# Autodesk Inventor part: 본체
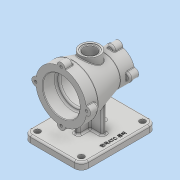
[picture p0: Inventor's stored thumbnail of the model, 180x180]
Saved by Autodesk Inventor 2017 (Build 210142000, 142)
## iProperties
Part Number: 본체
Material: 일반
Document SubType Name: Modeling
Designer: mrc
Density: 1 g/cm^3
Appearance: 기본값
Mass: 381.324 g
Surface Area: 851.607 cm^2
Volume: 381.324 cm^3
Author: mrc
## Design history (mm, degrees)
sketch "스케치3"
  geometry: L1 (-50, 0)-(-50, 44); L2 (-50, 44)-(-30, 44); L3 (-30, 44)-(25, 27.5); L4 (25, 27.5)-(50, 27.5); L5 (50, 27.5)-(50, 0); L6 (50, 0)-(-50, 0); 2 further points
  constraints: 12 end point, 2 horizontal, 2 perpendicular, 1 coincident, 1 midpoint, 1 vertical
  dimensions: "d29" = 44 distance of L1.start L1.end; "d30" = 20 distance of L1.end L2.end; "d31" = 100 distance between parallel lines of L5 L1; "d32" = 27.5 distance of L4.end L5.end; "d33" = 25 distance of L3.end L4.end
node "스케치4"
revolve "회전1" stored, may be unused: angle "d34" = 90 deg
sketch "스케치5"
  geometry: L1 (65, -70)-(-65, -70); L2 (-65, -70)-(-65, -82); L3 (-65, -82)-(65, -82); L4 (65, -82)-(65, -70); 2 further points
  constraints: 8 end point, 2 parallel, 1 horizontal, 1 midpoint, 1 perpendicular, 1 vertical alignment
  dimensions: "d35" = 130 distance of L3.end L2.end; "d36" = 12 distance of L2.end L1.end; "d37" = 82 vertical distance of L3.end point (0, 0)
extrude "돌출1" join sketch "스케치5" stored distance "d38" = 100; taper "d39" = 0 deg
sketch "스케치6"
  geometry: L1 (-24, 2.047)-(24, 2.047); L2 (24, 2.047)-(24, -70); L3 (24, -70)-(-24, -70); L4 (-24, -70)-(-24, 2.047); L5 (-65, -70)-(65, -70) reference; 2 further points
  constraints: 8 end point, 2 midpoint, 2 parallel, 1 horizontal, 1 perpendicular
  dimensions: "d40" = 48 distance of L2.end L3.end
extrude "돌출2" join sketch "스케치6" stored distance "d41" = 8; taper "d42" = 0 deg
sketch "스케치7"
  geometry: L1 (25, -3.867)-(-25, -3.867); L2 (-25, -3.867)-(-25, -70); L3 (-25, -70)-(25, -70); L4 (25, -70)-(25, -3.867); L5 (4, -70)-(-4, -70) reference; 2 further points
  constraints: 8 end point, 2 midpoint, 2 parallel, 1 horizontal, 1 perpendicular
  dimensions: "d43" = 50 distance of L3.end L2.end
extrude "돌출3" join sketch "스케치7" stored distance "d44" = 8; taper "d45" = 0 deg
sketch "스케치8"
  geometry: C1 r 32 at (0, 0); 1 further point
  constraints: 1 centre point, 1 coincident
  dimensions: "d46" = 64 diameter of C1
extrude "돌출4" cut sketch "스케치8" distance "d47" = 23; taper "d48" = 0 deg
sketch "스케치9"
  geometry: C1 r 26 at (0, 0); 1 further point
  constraints: 1 centre point, 1 coincident
  dimensions: "d49" = 52 diameter of C1
extrude "돌출5" cut sketch "스케치9" distance "d50" = 47; taper "d51" = 0 deg
sketch "스케치10"
  geometry: C1 r 20 at (0, 0); 1 further point
  constraints: 1 centre point, 1 coincident
  dimensions: "d52" = 40 diameter of C1
extrude "돌출6" cut sketch "스케치10" distance "d53" = 30; taper "d54" = 0 deg
sketch "스케치11"
  geometry: C1 r 7 at (0, 44); 2 further points
  constraints: 1 centre point, 1 vertical alignment, 1 other
  dimensions: "d55" = 14 diameter of C1
extrude "돌출7" join sketch "스케치11" distance "d56" = 15; taper "d57" = 0 deg
hole "구멍1" diameter "d60" = 4.459; stored, may be unused: countersink angle "d64" = 90 deg, drill point angle "d66" = 118 deg; dims "d58" = 10, "d59" = 10, "d61" = 9, "d62" = 4, "d63" = 2, "d65" = 11
sketch "스케치12"
  geometry: C1 r 7 at (0, -27.5); 2 further points
  constraints: 1 centre point, 1 vertical alignment, 1 other
  dimensions: "d70" = 14 diameter of C1
extrude "돌출8" join sketch "스케치12" distance "d71" = 15; taper "d72" = 0 deg
hole "구멍2" diameter "d75" = 4.459; stored, may be unused: countersink angle "d79" = 90 deg, drill point angle "d81" = 118 deg; dims "d73" = 10, "d74" = 10, "d76" = 9, "d77" = 4, "d78" = 2, "d80" = 11
node "작업 평면1"
sketch "스케치13"
  geometry: C1 r 17 at (0, 0); 1 further point
  constraints: 1 centre point, 1 coincident
  dimensions: "d86" = 34 diameter of C1
extrude "돌출9" join sketch "스케치13" stored distance "d87" = 15; taper "d88" = 0 deg
sketch "스케치14"
  geometry: C1 r 14 at (0, 0); 1 further point
  constraints: 1 centre point, 1 coincident
  dimensions: "d89" = 28 diameter of C1
extrude "돌출10" cut sketch "스케치14" distance "d90" = 1; taper "d91" = 0 deg
sketch "스케치15"
  geometry: C1 r 11 at (0, 0); 1 further point
  constraints: 1 centre point, 1 coincident
  dimensions: "d92" = 22 diameter of C1
extrude "돌출11" cut sketch "스케치15" stored distance "d93" = 1; taper "d94" = 0 deg
fillet "모깎기1" dims "d95" = 12
hole "구멍3" diameter "d98" = 10; stored, may be unused: countersink angle "d102" = 90 deg, drill point angle "d104" = 0 deg; dims "d96" = 10, "d97" = 10, "d99" = 9, "d100" = 4, "d101" = 2, "d103" = 40.75
fillet "모깎기2" dims "d109" = 1
fillet "모깎기3" dims "d110" = 3
fillet "모깎기6" dims "d113" = 3
fillet "모깎기7" dims "d114" = 3
chamfer "모따기1" distance "d115" = 1; stored, may be unused: second distance "d116" = 2, angle "d117" = 45 deg
fillet "모깎기8" dims "d118" = 3
fillet "모깎기9" dims "d119" = 3
chamfer "모따기2" distance "d120" = 1; stored, may be unused: second distance "d121" = 2, angle "d122" = 45 deg
fillet "모깎기10" dims "d123" = 3, "d124" = 1
fillet "모깎기11" dims "d125" = 1
fillet "모깎기12" dims "d126" = 3, "d127" = 1
sketch "스케치19"
  geometry: 1 further point
fillet "모깎기13" dims "d134" = 3
sketch "스케치20"
  geometry: L1 (72.253, -96.126)-(72.253, -27.874); L2 (72.253, -27.874)-(83.747, -27.874); L3 (83.747, -27.874)-(83.747, -96.126); L4 (83.747, -96.126)-(72.253, -96.126); L5 (78, -96.126)-(78, -27.874); L6 (72.253, -62)-(83.747, -62); L7 (88, -115)-(88, -9) reference; 2 further points
  constraints: 5 midpoint, 4 end point, 1 horizontal alignment, 2 other
  dimensions: "d135" = 10 distance between parallel lines of L7 L5
extrude "돌출12" join sketch "스케치20" distance "d136" = 0.5; taper "d137" = 0 deg
fillet "모깎기14" dims "d138" = 3, "d139" = 1
fillet "모깎기15" dims "d140" = 1
fillet "모깎기16" dims "d141" = 1
node "솔리드1"
pattern_linear "직사각형 패턴1"
pattern_circular "원형 패턴3" dims angle "d129" = 360 deg
pattern_circular "원형 패턴4" dims angle "d132" = 360 deg
other parameters: "d85" = 45
